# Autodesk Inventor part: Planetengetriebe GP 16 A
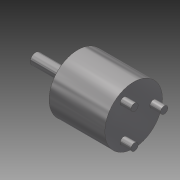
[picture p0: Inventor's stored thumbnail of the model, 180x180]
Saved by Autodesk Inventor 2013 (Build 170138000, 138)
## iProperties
Created: 2012-07
Part Number: Planetengetriebe GP 16 A
Material: Edelstahl
Document SubType Name: Modeling
Designer: rYan
Mass: 26.4198 g
Surface Area: 14.0202 cm^2
Volume: 3.26978 cm^3
Density: 8.08 g/cm^3
Author: rYan
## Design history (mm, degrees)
sketch "Skizze1"
  geometry: L1 (-13.625, 0)-(-13.625, 1.5); L2 (-13.625, 1.5)-(-4.475, 1.5); L3 (-4.475, 1.5)-(-4.475, 3); L4 (-4.475, 3)-(-1.875, 3); L5 (-1.875, 3)-(-1.875, 8); L6 (-1.875, 8)-(13.625, 8); L7 (13.625, 8)-(13.625, 0); L8 (13.625, 0)-(-13.625, 0); L9 (0, 9.6)-(0, -1.6) reference; L10 (-19.075, 0)-(19.075, 0) reference; 1 further point
  constraints: 16 end point, 6 parallel, 1 collinear, 1 perpendicular, 1 vertical, 1 other
  dimensions: "d0" = 3 diameter of L2 L8; "d2" = 6 diameter of L4 L8; "d3" = 16 diameter of L6 L8; "d4" = 15.5 distance of L5.end L6.end; "d5" = 2.6 distance of L3.end L4.end; "d6" = 11.75 distance between parallel lines of L5 L1
revolve "Umdrehung1" sketch "Skizze1" stored, may be unused: angle "d7" = 90 deg
sketch "Skizze2" dims "d8" = 10
  geometry: L1 (0, 11.2)-(0, -11.2) reference; C1 r 8 at (0, 0) reference; 3 further points
  constraints: 1 coincident, 1 point on line, 1 vertical alignment, 2 other
hole "Bohrung1" sketch "Skizze2" at (0, 5) diameter "d10" = 1.567; stored, may be unused: countersink angle "d14" = 90 deg, drill point angle "d16" = 0 deg; dims "d11" = 6, "d12" = 4, "d13" = 2, "d15" = 3
pattern_circular "Runde Anordnung1" dims angle "d18" = 360 deg
sketch "Skizze3"
  geometry: L1 (-11.2, 0)-(11.2, 0) reference; L2 (-4.664, -1.5)-(5.169, -1.5); L3 (-2, 1.5)-(2, 1.5); L4 (2, 1.5)-(2, 1.3); L5 (2, 1.3)-(-2, 1.3); L6 (-2, 1.3)-(-2, 1.5); L7 (0, 11.2)-(0, -11.2) reference; C1 r 1.5 at (0, 0) reference; 1 further point
  constraints: 10 end point, 3 parallel, 2 tangent, 1 horizontal, 1 perpendicular, 1 other
  dimensions: "d22" = 2.8 distance between parallel lines of L5 L2; "d24" = 4 distance of L3.start L3.end
extrude "Extrusion1" cut sketch "Skizze3" distance "d25" = 7.8; taper "d26" = 0 deg
sketch "Skizze4" dims "d27" = 11
  geometry: L1 (0, -11.2)-(0, 11.2) reference; C1 r 1 at (0, 5.5); 2 further points
  constraints: 1 centre point, 1 coincident, 1 point on line, 1 vertical alignment, 2 other
  dimensions: "d29" = 2 diameter of C1
extrude "Extrusion2" join sketch "Skizze4" distance "d30" = 3; taper "d31" = 0 deg
pattern_circular "Runde Anordnung2" dims angle "d33" = 360 deg
node "Volumenkörper1"
